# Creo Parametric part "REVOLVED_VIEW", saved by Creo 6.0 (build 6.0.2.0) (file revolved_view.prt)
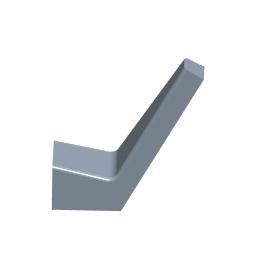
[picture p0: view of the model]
Units: Inch lbm Second (Pro/E Default); INCH, POUND, SECS

Created from: INLBS_PART_SOLID.PRT

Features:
  1. datum plane "RIGHT"
  2. datum plane "TOP"
  3. datum plane "FRONT"
  4. coordinate system
  5. extrusion "Extrude 1"
  6. extruded cut "Extrude 2"
  7. round "Round 1"
  8. round "Round 2"

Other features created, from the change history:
  extrusion "Extrude 1"
  extruded cut "Extrude 2"
  round "Round 1" (2 times)
  planar section "XSEC0001"
  planar section "XSEC0002"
